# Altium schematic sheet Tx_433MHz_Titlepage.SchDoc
size 594 x 420 mm; APPROVED: Yes; Border_Classification: ?; CmpIndex: 0; Description: 433MHz Transmitter & Receiver; ENGINEER: KuRe/SnLe; REVIEWED: Yes; REVISION: 2.0; SymIndex: 0
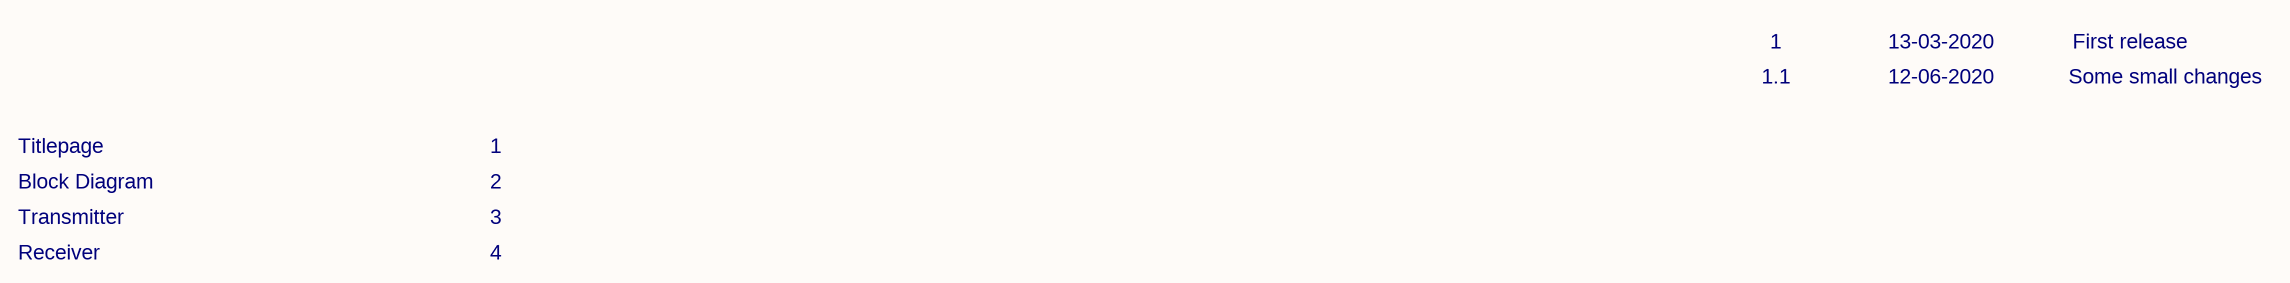
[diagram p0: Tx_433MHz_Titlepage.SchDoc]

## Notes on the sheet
- 1
- 13-03-2020
- First release
- 1.1
- 12-06-2020
- Some small changes
- Titlepage
- Transmitter
- Block Diagram
- 2
- 3
- Receiver
- 4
